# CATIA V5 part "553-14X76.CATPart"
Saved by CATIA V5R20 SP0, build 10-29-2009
Part number: 553-14x76
Definition: NONE
Nomenclature: 553-14x76
Source: Unknown
Description: 553-14x76
Bounding box of the stored display mesh (mm): x 0 to 76, y -12.5 to 12.5, z -12.5 to 12.5
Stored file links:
  C:\Users\Utente\Desktop\IO LAVORO\3D X SITO CF\X SITO\PLASTICA\553\553-14X76.CATPart
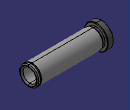
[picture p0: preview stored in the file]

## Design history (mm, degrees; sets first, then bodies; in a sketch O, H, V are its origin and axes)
Body1 "553-14x76" (main body)
  Solid1: solid without history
